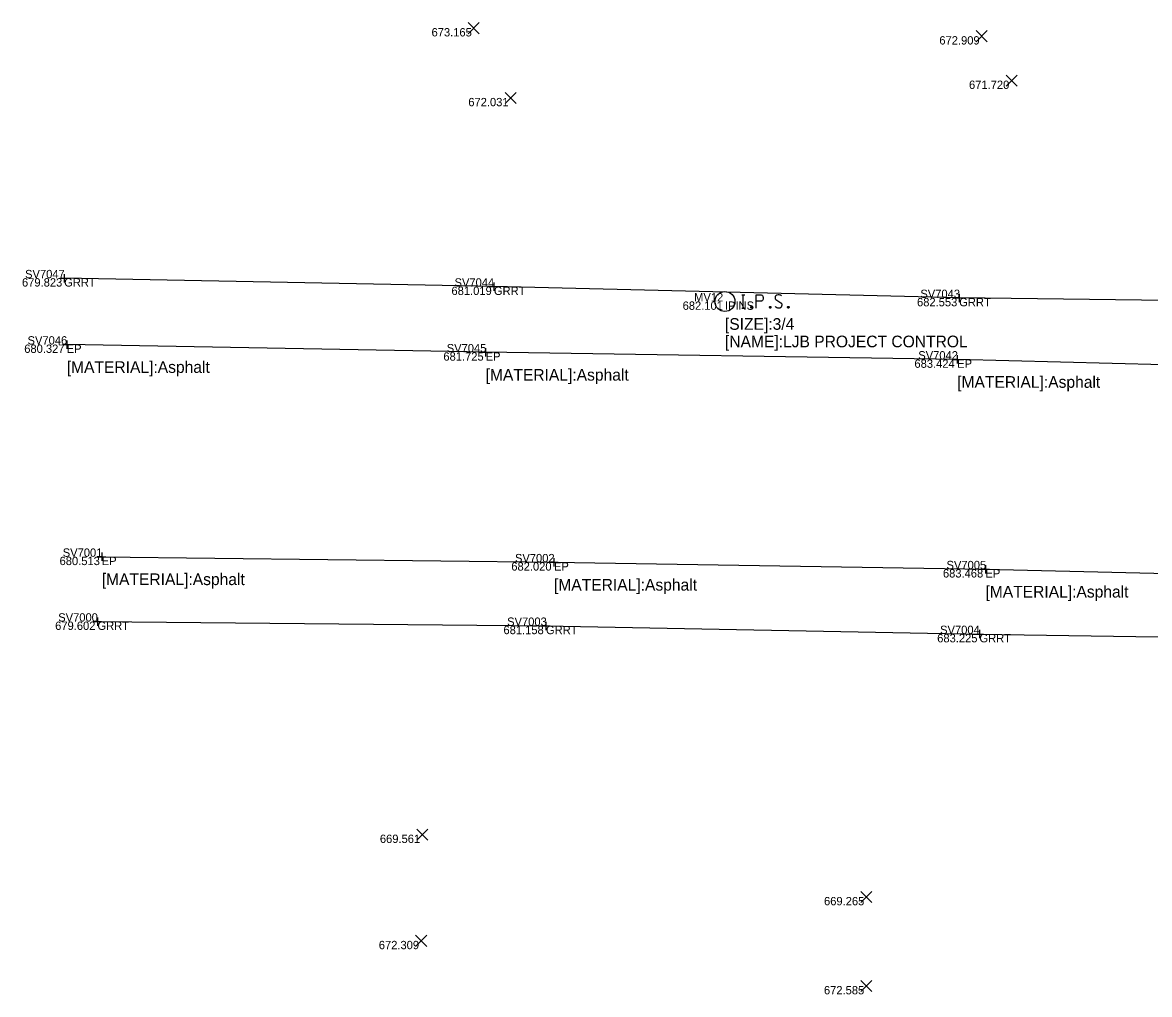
# Model space of a CAD drawing. Extents: x 1660019 to 1662995, y 619975 to 620342.
# Drawn here: x 1660587.9 to 1660723.1, y 620181.6 to 620298.2 of the extents above; entities that cross this region are included whole.
import ezdxf

# ---------------------------------------------------------------- set-up
doc = ezdxf.new("R2010")
doc.units = 0
for name, color, linetype in [('BR_X_Rail_Object', 7, 'Continuous'), ('PV_X_EOP', 7, 'Continuous'), ('RD_P_GR_Lt', 7, 'Continuous'), ('RD_P_GR_Rt', 7, 'Continuous'), ('RD_X_GR_Bar', 7, 'Continuous'), ('RD_X_GR_Rt', 7, 'Continuous'), ('RD_X_Wall', 7, 'Continuous'), ('SV_P_Mon_Cells_Set_Text', 7, 'Continuous'), ('SV_X_Break_Lines', 7, 'Continuous'), ('SV_X_Text', 7, 'Continuous')]:
    doc.layers.add(name, color=color, linetype=linetype)

msp = doc.modelspace()

# ---------------------------------------------------------------- linework, layer by layer
at = {"layer": 'PV_X_EOP'}
for points in [[(1661208.92, 620246.9), (1661156.94, 620248.21), (1661087.29, 620250.6), (1661037.39, 620250.48), (1660981.01, 620252.16), (1660916.41, 620253.34), (1660855.2, 620254.44), (1660801.44, 620255.57), (1660749.64, 620256.49), (1660700.03, 620257.78), (1660643.44, 620258.64), (1660593.17, 620259.57)], [(1660597.37, 620234.1), (1660651.64, 620233.44), (1660703.42, 620232.61), (1660757.32, 620231.35), (1660809.76, 620230.12), (1660857.03, 620229.26), (1660910.07, 620228.44), (1660968.25, 620227.38), (1661028.27, 620226.15), (1661081.58, 620225.11), (1661140.41, 620223.53), (1661201.71, 620222.7)]]:
    msp.add_lwpolyline(points, dxfattribs=at)
at = {"layer": 'RD_P_GR_Lt'}
for p, q in [((1660592.36, 620267.53), (1660593.36, 620267.53)), ((1660592.86, 620268.03), (1660592.86, 620267.03)), ((1660592.86, 620267.53), (1660592.86, 620267.53)), ((1660643.93, 620266.52), (1660644.93, 620266.52)), ((1660644.43, 620267.02), (1660644.43, 620266.02)), ((1660644.43, 620266.52), (1660644.43, 620266.52)), ((1660699.77, 620265.16), (1660700.77, 620265.16)), ((1660700.27, 620265.66), (1660700.27, 620264.66)), ((1660700.27, 620265.16), (1660700.27, 620265.16)), ((1660592.67, 620259.57), (1660593.67, 620259.57)), ((1660593.17, 620260.07), (1660593.17, 620259.07)), ((1660593.17, 620259.57), (1660593.17, 620259.57)), ((1660642.94, 620258.64), (1660643.94, 620258.64)), ((1660643.44, 620259.14), (1660643.44, 620258.14)), ((1660643.44, 620258.64), (1660643.44, 620258.64)), ((1660700.03, 620258.28), (1660700.03, 620257.28)), ((1660699.53, 620257.78), (1660700.53, 620257.78)), ((1660700.03, 620257.78), (1660700.03, 620257.78)), ((1660596.87, 620234.1), (1660597.87, 620234.1)), ((1660597.37, 620234.6), (1660597.37, 620233.6)), ((1660597.37, 620234.1), (1660597.37, 620234.1)), ((1660651.64, 620233.94), (1660651.64, 620232.94)), ((1660651.14, 620233.44), (1660652.14, 620233.44)), ((1660651.64, 620233.44), (1660651.64, 620233.44)), ((1660702.92, 620232.61), (1660703.92, 620232.61)), ((1660703.42, 620233.11), (1660703.42, 620232.11)), ((1660703.42, 620232.61), (1660703.42, 620232.61)), ((1660596.36, 620226.32), (1660597.36, 620226.32)), ((1660596.86, 620226.82), (1660596.86, 620225.82)), ((1660596.86, 620226.32), (1660596.86, 620226.32)), ((1660650.18, 620225.81), (1660651.18, 620225.81)), ((1660650.68, 620226.31), (1660650.68, 620225.31)), ((1660650.68, 620225.81), (1660650.68, 620225.81)), ((1660702.2, 620224.83), (1660703.2, 620224.83)), ((1660702.7, 620225.33), (1660702.7, 620224.33)), ((1660702.7, 620224.83), (1660702.7, 620224.83))]:
    msp.add_line(p, q, dxfattribs=at)
at = {"layer": 'RD_P_GR_Rt'}
for p, q in [((1660641.35, 620296.88), (1660642.68, 620298.22)), ((1660641.35, 620298.22), (1660642.68, 620296.88)), ((1660702.31, 620295.92), (1660703.64, 620297.25)), ((1660702.31, 620297.25), (1660703.64, 620295.92)), ((1660705.9, 620290.58), (1660707.23, 620291.92)), ((1660705.9, 620291.92), (1660707.23, 620290.58)), ((1660645.77, 620288.5), (1660647.11, 620289.84)), ((1660645.77, 620289.84), (1660647.11, 620288.5)), ((1660635.17, 620200.09), (1660636.5, 620201.42)), ((1660635.17, 620201.42), (1660636.5, 620200.09)), ((1660688.45, 620192.6), (1660689.78, 620193.94)), ((1660688.45, 620193.94), (1660689.78, 620192.6)), ((1660635.03, 620187.33), (1660636.37, 620188.67)), ((1660635.03, 620188.67), (1660636.37, 620187.33)), ((1660688.45, 620181.91), (1660689.78, 620183.25)), ((1660688.45, 620183.25), (1660689.78, 620181.91))]:
    msp.add_line(p, q, dxfattribs=at)
at = {"layer": 'RD_X_GR_Rt'}
for points in [[(1661224.69, 620250.79), (1661156.18, 620253.35), (1661087.54, 620257.19), (1661037.26, 620258.5), (1660981.37, 620259.47), (1660918.68, 620260.81), (1660856.77, 620262.08), (1660800.7, 620262.74), (1660750.31, 620264.54), (1660700.27, 620265.16), (1660644.43, 620266.52), (1660592.86, 620267.53)], [(1660596.86, 620226.32), (1660650.68, 620225.81), (1660702.7, 620224.83), (1660759.05, 620223.97), (1660808.86, 620222.78), (1660856.77, 620221.69), (1660908.98, 620220.55), (1660971.26, 620219.59), (1661027.54, 620217.92), (1661083.51, 620217.29), (1661139.61, 620218.11), (1661215.13, 620218.24)]]:
    msp.add_lwpolyline(points, dxfattribs=at)
at = {"layer": 'SV_X_Break_Lines'}
for points in [[(1660674.18, 620265.54), (1660674.53, 620265.54)], [(1660674.35, 620263.94), (1660674.35, 620265.54)], [(1660675.92, 620263.94), (1660675.92, 620265.54), (1660676.45, 620265.54), (1660676.5, 620265.53), (1660676.58, 620265.5), (1660676.61, 620265.48), (1660676.65, 620265.45), (1660676.69, 620265.39), (1660676.72, 620265.32), (1660676.75, 620265.22), (1660676.75, 620265.07), (1660676.73, 620265.02), (1660676.71, 620264.95), (1660676.67, 620264.86), (1660676.62, 620264.82), (1660676.59, 620264.8), (1660676.54, 620264.77), (1660676.45, 620264.76), (1660675.92, 620264.76)], [(1660678.93, 620265.43), (1660678.91, 620265.45), (1660678.87, 620265.48), (1660678.77, 620265.51), (1660678.65, 620265.54), (1660678.56, 620265.54), (1660678.53, 620265.54), (1660678.39, 620265.5), (1660678.27, 620265.43), (1660678.19, 620265.32), (1660678.17, 620265.22), (1660678.17, 620265.15), (1660678.19, 620265.05), (1660678.28, 620264.96), (1660678.88, 620264.58), (1660678.94, 620264.53), (1660678.96, 620264.48), (1660678.98, 620264.4), (1660678.98, 620264.33), (1660678.97, 620264.25), (1660678.96, 620264.2), (1660678.94, 620264.14), (1660678.92, 620264.09), (1660678.89, 620264.05), (1660678.86, 620264.01), (1660678.83, 620263.99), (1660678.78, 620263.96), (1660678.75, 620263.95), (1660678.65, 620263.94), (1660678.5, 620263.94), (1660678.4, 620263.96), (1660678.26, 620264.05), (1660678.17, 620264.13)], [(1660674.18, 620263.94), (1660674.53, 620263.94)], [(1660675.31, 620264.15), (1660675.37, 620264.15), (1660675.4, 620264.13), (1660675.43, 620264.08), (1660675.43, 620264.01), (1660675.4, 620263.96), (1660675.37, 620263.94), (1660675.31, 620263.94), (1660675.28, 620263.96), (1660675.25, 620264.01), (1660675.25, 620264.08), (1660675.28, 620264.13), (1660675.31, 620264.15)], [(1660677.56, 620264.15), (1660677.62, 620264.15), (1660677.65, 620264.13), (1660677.68, 620264.08), (1660677.68, 620264.01), (1660677.65, 620263.96), (1660677.62, 620263.94), (1660677.56, 620263.94), (1660677.53, 620263.96), (1660677.49, 620264.01), (1660677.49, 620264.08), (1660677.53, 620264.13), (1660677.56, 620264.15)], [(1660679.74, 620264.15), (1660679.8, 620264.15), (1660679.83, 620264.13), (1660679.86, 620264.08), (1660679.86, 620264.01), (1660679.83, 620263.96), (1660679.8, 620263.94), (1660679.74, 620263.94), (1660679.71, 620263.96), (1660679.68, 620264.01), (1660679.68, 620264.08), (1660679.71, 620264.13), (1660679.74, 620264.15)]]:
    msp.add_lwpolyline(points, dxfattribs=at)
msp.add_circle((1660672.16, 620264.74), 1.2, dxfattribs=at)

# ---------------------------------------------------------------- texts
at = {"layer": 'BR_X_Rail_Object'}
for s, p in [('GRRT', (1660592.86, 620266.53)), ('GRRT', (1660644.43, 620265.52)), ('GRRT', (1660700.27, 620264.16)), ('IPINS', (1660672.16, 620263.74)), ('EP', (1660593.17, 620258.57)), ('EP', (1660643.44, 620257.64)), ('EP', (1660700.03, 620256.78)), ('EP', (1660597.37, 620233.1)), ('EP', (1660651.64, 620232.44)), ('EP', (1660703.42, 620231.61)), ('GRRT', (1660596.86, 620225.32)), ('GRRT', (1660650.68, 620224.81)), ('GRRT', (1660702.7, 620223.83))]:
    msp.add_text(s, height=1, dxfattribs=at).set_placement(p)
at = {"layer": 'RD_X_GR_Bar'}
for s, p in [('673.165', (1660636.95, 620296.55)), ('672.909', (1660697.89, 620295.58)), ('671.720', (1660701.45, 620290.25)), ('672.031', (1660641.36, 620288.17)), ('679.823', (1660587.8, 620266.53)), ('681.019', (1660639.34, 620265.52)), ('682.553', (1660695.21, 620264.16)), ('682.101', (1660667.08, 620263.74)), ('680.327', (1660588.07, 620258.57)), ('681.725', (1660638.37, 620257.64)), ('683.424', (1660694.9, 620256.78)), ('680.513', (1660592.31, 620233.1)), ('682.020', (1660646.52, 620232.44)), ('683.468', (1660698.32, 620231.61)), ('679.602', (1660591.78, 620225.32)), ('681.158', (1660645.58, 620224.81)), ('683.225', (1660697.63, 620223.83)), ('669.561', (1660630.75, 620199.75)), ('669.265', (1660684.05, 620192.27)), ('672.309', (1660630.62, 620187)), ('672.585', (1660684.04, 620181.58))]:
    msp.add_text(s, height=1, dxfattribs=at).set_placement(p)
at = {"layer": 'RD_X_Wall'}
for s, p in [('SV7047', (1660588.17, 620267.53)), ('SV7044', (1660639.71, 620266.52)), ('SV7043', (1660695.61, 620265.16)), ('MV12', (1660668.46, 620264.74)), ('SV7046', (1660588.47, 620259.57)), ('SV7045', (1660638.77, 620258.64)), ('SV7042', (1660695.36, 620257.78)), ('SV7001', (1660592.69, 620234.1)), ('SV7002', (1660646.96, 620233.44)), ('SV7005', (1660698.75, 620232.61)), ('SV7000', (1660592.15, 620226.32)), ('SV7003', (1660646.02, 620225.81)), ('SV7004', (1660697.98, 620224.83))]:
    msp.add_text(s, height=1, dxfattribs=at).set_placement(p)
at = {"layer": 'SV_P_Mon_Cells_Set_Text'}
for s, p in [('[SIZE]:3/4', (1660672.16, 620261.34)), ('[NAME]:LJB PROJECT CONTROL', (1660672.16, 620259.24))]:
    msp.add_text(s, height=1.4, dxfattribs=at).set_placement(p)
at = {"layer": 'SV_X_Text'}
for p in [(1660593.17, 620256.17), (1660643.44, 620255.24), (1660700.03, 620254.38), (1660597.37, 620230.7), (1660651.64, 620230.04), (1660703.42, 620229.21)]:
    msp.add_text('[MATERIAL]:Asphalt', height=1.4, dxfattribs=at).set_placement(p)

doc.saveas('drawing.dxf')
